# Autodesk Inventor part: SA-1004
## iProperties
Created: 2004-11
Part Number: SA-1004
Cost Center: 0 lbmass
Document SubType Name: Modeling
Designer: busseym
Manufacturer: Standard
Standards Organization: Custom
Stock Number: P-1267
Density: 1 g/cm^3
CAGE: 1LJX3
Dept. ID: Product Design
Description #2: ---
Finish #1: ---
Finish #2: ---
Material ID: ---
Project Number: ---
Author: busseym
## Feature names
1. Revolution1
2. Extrusion1
3. Extrusion2
